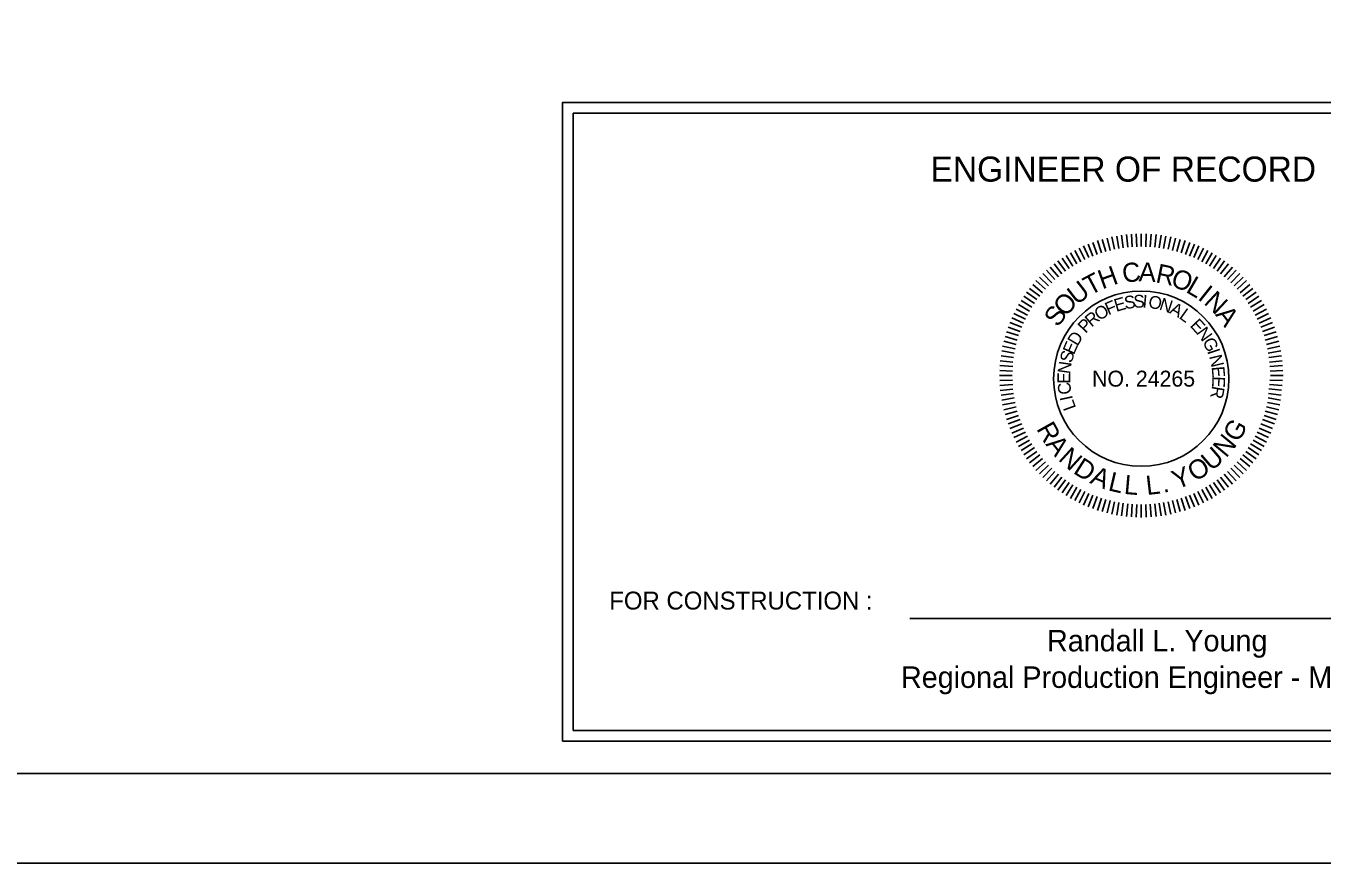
# Model space of a CAD drawing. Extents: x -796 to 2793, y -4650 to 4425.
# Drawn here: x 2234 to 2596, y 1000 to 1233.8 of the extents above; entities that cross this region are included whole.
import ezdxf

# ---------------------------------------------------------------- set-up
doc = ezdxf.new("R2010")
doc.units = 0
for name, color, linetype in [('RD_HC_CL', 7, 'Continuous'), ('RD_HC_Data', 7, 'Continuous'), ('RD_HC_Data_Tic', 7, 'Continuous'), ('RD_SHT_Bndy', 7, 'Continuous'), ('RD_TX_PEShield', 7, 'Continuous')]:
    doc.layers.add(name, color=color, linetype=linetype)

msp = doc.modelspace()

# ---------------------------------------------------------------- linework, layer by layer
at = {"layer": 'RD_HC_CL'}
msp.add_lwpolyline([(984.13, 2100), (2780.13, 2100), (2780.13, 1000), (984.13, 1000)], close=True, dxfattribs=at)
at = {"layer": 'RD_HC_Data'}
for p, q in [((2480.88, 1068.27), (2619.52, 1068.27)), ((2760, 1000), (1000, 1000)), ((1000, 1000), (2759.98, 1000))]:
    msp.add_line(p, q, dxfattribs=at)
for points in [[(1079.63, 2075.05), (2755.13, 2075.05), (2755.13, 1025), (1079.63, 1025)], [(2383.87, 1034.06), (2702.13, 1034.06), (2702.13, 1212.42), (2383.87, 1212.42)], [(2386.87, 1037.06), (2699.13, 1037.06), (2699.13, 1209.42), (2386.87, 1209.42)]]:
    msp.add_lwpolyline(points, close=True, dxfattribs=at)
at = {"layer": 'RD_TX_PEShield'}
for p, q in [((2531.98, 1169.54), (2530.65, 1172.84)), ((2531.98, 1169.54), (2530.65, 1172.84)), ((2533.16, 1169.99), (2531.94, 1173.33)), ((2533.16, 1169.99), (2531.94, 1173.33)), ((2534.33, 1170.44), (2533.23, 1173.83)), ((2534.33, 1170.44), (2533.23, 1173.83)), ((2535.55, 1170.77), (2534.57, 1174.18)), ((2535.55, 1170.77), (2534.57, 1174.18)), ((2536.76, 1171.09), (2535.9, 1174.54)), ((2536.76, 1171.09), (2535.9, 1174.54)), ((2537.98, 1171.42), (2537.24, 1174.9)), ((2537.98, 1171.42), (2537.24, 1174.9)), ((2539.22, 1171.61), (2538.6, 1175.12)), ((2539.22, 1171.61), (2538.6, 1175.12)), ((2540.46, 1171.81), (2539.97, 1175.33)), ((2540.46, 1171.81), (2539.97, 1175.33)), ((2541.7, 1172.01), (2541.33, 1175.55)), ((2541.7, 1172.01), (2541.33, 1175.55)), ((2542.96, 1172.07), (2542.71, 1175.62)), ((2542.96, 1172.07), (2542.71, 1175.62)), ((2544.21, 1172.14), (2544.09, 1175.69)), ((2544.21, 1172.14), (2544.09, 1175.69)), ((2545.47, 1172.2), (2545.47, 1175.76)), ((2545.47, 1172.2), (2545.47, 1175.76)), ((2546.73, 1172.14), (2546.85, 1175.69)), ((2546.73, 1172.14), (2546.85, 1175.69)), ((2547.98, 1172.07), (2548.23, 1175.62)), ((2547.98, 1172.07), (2548.23, 1175.62)), ((2549.24, 1172.01), (2549.61, 1175.55)), ((2549.24, 1172.01), (2549.61, 1175.55)), ((2550.48, 1171.81), (2550.98, 1175.33)), ((2550.48, 1171.81), (2550.98, 1175.33)), ((2551.72, 1171.61), (2552.34, 1175.12)), ((2551.72, 1171.61), (2552.34, 1175.12)), ((2552.96, 1171.42), (2553.71, 1174.9)), ((2552.96, 1171.42), (2553.71, 1174.9)), ((2552.96, 1171.42), (2553.71, 1174.9)), ((2554.18, 1171.09), (2555.04, 1174.54)), ((2554.18, 1171.09), (2555.04, 1174.54)), ((2554.18, 1171.09), (2555.04, 1174.54)), ((2555.39, 1170.77), (2556.37, 1174.18)), ((2555.39, 1170.77), (2556.37, 1174.18)), ((2555.39, 1170.77), (2556.37, 1174.18)), ((2556.61, 1170.44), (2557.71, 1173.83)), ((2556.61, 1170.44), (2557.71, 1173.83)), ((2556.61, 1170.44), (2557.71, 1173.83)), ((2557.78, 1169.99), (2559, 1173.33)), ((2557.78, 1169.99), (2559, 1173.33)), ((2557.78, 1169.99), (2559, 1173.33)), ((2558.96, 1169.54), (2560.29, 1172.84)), ((2558.96, 1169.54), (2560.29, 1172.84)), ((2558.96, 1169.54), (2560.29, 1172.84)), ((2526.39, 1166.69), (2524.51, 1169.71)), ((2526.39, 1166.69), (2524.51, 1169.71)), ((2527.45, 1167.38), (2525.67, 1170.46)), ((2527.45, 1167.38), (2525.67, 1170.46)), ((2528.57, 1167.95), (2526.9, 1171.09)), ((2528.57, 1167.95), (2526.9, 1171.09)), ((2529.69, 1168.52), (2528.13, 1171.71)), ((2529.69, 1168.52), (2528.13, 1171.71)), ((2530.81, 1169.09), (2529.36, 1172.34)), ((2530.81, 1169.09), (2529.36, 1172.34)), ((2560.13, 1169.09), (2561.58, 1172.34)), ((2560.13, 1169.09), (2561.58, 1172.34)), ((2560.13, 1169.09), (2561.58, 1172.34)), ((2561.25, 1168.52), (2562.81, 1171.71)), ((2561.25, 1168.52), (2562.81, 1171.71)), ((2561.25, 1168.52), (2562.81, 1171.71)), ((2562.37, 1167.95), (2564.04, 1171.09)), ((2562.37, 1167.95), (2564.04, 1171.09)), ((2562.37, 1167.95), (2564.04, 1171.09)), ((2563.49, 1167.38), (2565.27, 1170.46)), ((2563.49, 1167.38), (2565.27, 1170.46)), ((2563.49, 1167.38), (2565.27, 1170.46)), ((2564.55, 1166.69), (2566.43, 1169.71)), ((2564.55, 1166.69), (2566.43, 1169.71)), ((2564.55, 1166.69), (2566.43, 1169.71)), ((2521.35, 1162.95), (2518.97, 1165.59)), ((2521.35, 1162.95), (2518.97, 1165.59)), ((2522.33, 1163.74), (2520.04, 1166.46)), ((2522.33, 1163.74), (2520.04, 1166.46)), ((2523.31, 1164.53), (2521.12, 1167.33)), ((2523.31, 1164.53), (2521.12, 1167.33)), ((2524.28, 1165.32), (2522.19, 1168.2)), ((2524.28, 1165.32), (2522.19, 1168.2)), ((2525.34, 1166.01), (2523.35, 1168.95)), ((2525.34, 1166.01), (2523.35, 1168.95)), ((2565.6, 1166.01), (2567.59, 1168.95)), ((2565.6, 1166.01), (2567.59, 1168.95)), ((2565.6, 1166.01), (2567.59, 1168.95)), ((2566.66, 1165.32), (2568.75, 1168.2)), ((2566.66, 1165.32), (2568.75, 1168.2)), ((2566.66, 1165.32), (2568.75, 1168.2)), ((2567.64, 1164.53), (2569.82, 1167.33)), ((2567.64, 1164.53), (2569.82, 1167.33)), ((2567.64, 1164.53), (2569.82, 1167.33)), ((2568.61, 1163.74), (2570.9, 1166.46)), ((2568.61, 1163.74), (2570.9, 1166.46)), ((2568.61, 1163.74), (2570.9, 1166.46)), ((2569.59, 1162.95), (2571.97, 1165.59)), ((2569.59, 1162.95), (2571.97, 1165.59)), ((2569.59, 1162.95), (2571.97, 1165.59)), ((2518.68, 1160.28), (2516.04, 1162.66)), ((2518.68, 1160.28), (2516.04, 1162.66)), ((2519.57, 1161.17), (2517.02, 1163.64)), ((2519.57, 1161.17), (2517.02, 1163.64)), ((2520.46, 1162.06), (2517.99, 1164.61)), ((2520.46, 1162.06), (2517.99, 1164.61)), ((2570.48, 1162.06), (2572.95, 1164.61)), ((2570.48, 1162.06), (2572.95, 1164.61)), ((2570.48, 1162.06), (2572.95, 1164.61)), ((2571.37, 1161.17), (2573.93, 1163.64)), ((2571.37, 1161.17), (2573.93, 1163.64)), ((2571.37, 1161.17), (2573.93, 1163.64)), ((2572.26, 1160.28), (2574.9, 1162.66)), ((2572.26, 1160.28), (2574.9, 1162.66)), ((2572.26, 1160.28), (2574.9, 1162.66)), ((2515.62, 1156.29), (2512.68, 1158.28)), ((2515.62, 1156.29), (2512.68, 1158.28)), ((2516.31, 1157.35), (2513.43, 1159.44)), ((2516.31, 1157.35), (2513.43, 1159.44)), ((2517.1, 1158.32), (2514.3, 1160.51)), ((2517.1, 1158.32), (2514.3, 1160.51)), ((2517.89, 1159.3), (2515.17, 1161.59)), ((2517.89, 1159.3), (2515.17, 1161.59)), ((2573.05, 1159.3), (2575.77, 1161.59)), ((2573.05, 1159.3), (2575.77, 1161.59)), ((2573.05, 1159.3), (2575.77, 1161.59)), ((2573.84, 1158.32), (2576.64, 1160.51)), ((2573.84, 1158.32), (2576.64, 1160.51)), ((2573.84, 1158.32), (2576.64, 1160.51)), ((2574.63, 1157.35), (2577.51, 1159.44)), ((2574.63, 1157.35), (2577.51, 1159.44)), ((2574.63, 1157.35), (2577.51, 1159.44)), ((2575.32, 1156.29), (2578.26, 1158.28)), ((2575.32, 1156.29), (2578.26, 1158.28)), ((2575.32, 1156.29), (2578.26, 1158.28)), ((2513.68, 1153.06), (2510.54, 1154.73)), ((2513.68, 1153.06), (2510.54, 1154.73)), ((2514.25, 1154.18), (2511.17, 1155.96)), ((2514.25, 1154.18), (2511.17, 1155.96)), ((2514.94, 1155.24), (2511.92, 1157.12)), ((2514.94, 1155.24), (2511.92, 1157.12)), ((2576, 1155.24), (2579.02, 1157.12)), ((2576, 1155.24), (2579.02, 1157.12)), ((2576, 1155.24), (2579.02, 1157.12)), ((2576.69, 1154.18), (2579.77, 1155.96)), ((2576.69, 1154.18), (2579.77, 1155.96)), ((2576.69, 1154.18), (2579.77, 1155.96)), ((2577.26, 1153.06), (2580.4, 1154.73)), ((2577.26, 1153.06), (2580.4, 1154.73)), ((2577.26, 1153.06), (2580.4, 1154.73)), ((2512.54, 1150.82), (2509.29, 1152.27)), ((2512.54, 1150.82), (2509.29, 1152.27)), ((2513.11, 1151.94), (2509.92, 1153.5)), ((2513.11, 1151.94), (2509.92, 1153.5)), ((2577.83, 1151.94), (2581.02, 1153.5)), ((2577.83, 1151.94), (2581.02, 1153.5)), ((2577.83, 1151.94), (2581.02, 1153.5)), ((2578.4, 1150.82), (2581.65, 1152.27)), ((2578.4, 1150.82), (2581.65, 1152.27)), ((2578.4, 1150.82), (2581.65, 1152.27)), ((2511.19, 1147.3), (2507.8, 1148.4)), ((2511.19, 1147.3), (2507.8, 1148.4)), ((2511.64, 1148.47), (2508.3, 1149.69)), ((2511.64, 1148.47), (2508.3, 1149.69)), ((2512.09, 1149.65), (2508.79, 1150.98)), ((2512.09, 1149.65), (2508.79, 1150.98)), ((2578.85, 1149.65), (2582.15, 1150.98)), ((2578.85, 1149.65), (2582.15, 1150.98)), ((2578.85, 1149.65), (2582.15, 1150.98)), ((2579.3, 1148.47), (2582.64, 1149.69)), ((2579.3, 1148.47), (2582.64, 1149.69)), ((2579.3, 1148.47), (2582.64, 1149.69)), ((2579.75, 1147.3), (2583.14, 1148.4)), ((2579.75, 1147.3), (2583.14, 1148.4)), ((2579.75, 1147.3), (2583.14, 1148.4)), ((2510.21, 1143.65), (2506.73, 1144.39)), ((2510.21, 1143.65), (2506.73, 1144.39)), ((2510.54, 1144.87), (2507.09, 1145.73)), ((2510.54, 1144.87), (2507.09, 1145.73)), ((2510.86, 1146.08), (2507.45, 1147.06)), ((2510.86, 1146.08), (2507.45, 1147.06)), ((2580.08, 1146.08), (2583.5, 1147.06)), ((2580.08, 1146.08), (2583.5, 1147.06)), ((2580.08, 1146.08), (2583.5, 1147.06)), ((2580.4, 1144.87), (2583.85, 1145.73)), ((2580.4, 1144.87), (2583.85, 1145.73)), ((2580.4, 1144.87), (2583.85, 1145.73)), ((2580.73, 1143.65), (2584.21, 1144.39)), ((2580.73, 1143.65), (2584.21, 1144.39)), ((2580.73, 1143.65), (2584.21, 1144.39)), ((2509.62, 1139.93), (2506.08, 1140.3)), ((2509.62, 1139.93), (2506.08, 1140.3)), ((2509.82, 1141.17), (2506.3, 1141.67)), ((2509.82, 1141.17), (2506.3, 1141.67)), ((2510.02, 1142.41), (2506.52, 1143.03)), ((2510.02, 1142.41), (2506.52, 1143.03)), ((2580.92, 1142.41), (2584.43, 1143.03)), ((2580.92, 1142.41), (2584.43, 1143.03)), ((2580.92, 1142.41), (2584.43, 1143.03)), ((2581.12, 1141.17), (2584.64, 1141.67)), ((2581.12, 1141.17), (2584.64, 1141.67)), ((2581.12, 1141.17), (2584.64, 1141.67)), ((2581.32, 1139.93), (2584.86, 1140.3)), ((2581.32, 1139.93), (2584.86, 1140.3)), ((2581.32, 1139.93), (2584.86, 1140.3)), ((2509.49, 1137.42), (2505.94, 1137.54)), ((2509.49, 1137.42), (2505.94, 1137.54)), ((2509.56, 1138.67), (2506.01, 1138.92)), ((2509.56, 1138.67), (2506.01, 1138.92)), ((2581.38, 1138.67), (2584.93, 1138.92)), ((2581.38, 1138.67), (2584.93, 1138.92)), ((2581.38, 1138.67), (2584.93, 1138.92)), ((2581.45, 1137.42), (2585, 1137.54)), ((2581.45, 1137.42), (2585, 1137.54)), ((2581.45, 1137.42), (2585, 1137.54)), ((2509.43, 1136.16), (2505.87, 1136.16)), ((2509.43, 1136.16), (2505.87, 1136.16)), ((2509.49, 1134.9), (2505.94, 1134.78)), ((2509.49, 1134.9), (2505.94, 1134.78)), ((2509.56, 1133.65), (2506.01, 1133.4)), ((2509.56, 1133.65), (2506.01, 1133.4)), ((2581.25, 1133.66), (2584.79, 1133.41)), ((2581.25, 1133.66), (2584.79, 1133.41)), ((2581.38, 1134.91), (2584.93, 1134.78)), ((2581.38, 1134.91), (2584.93, 1134.78)), ((2581.52, 1136.16), (2585.08, 1136.16)), ((2581.52, 1136.16), (2585.08, 1136.16)), ((2581.52, 1136.16), (2585.08, 1136.16)), ((2509.62, 1132.39), (2506.08, 1132.02)), ((2509.62, 1132.39), (2506.08, 1132.02)), ((2509.82, 1131.15), (2506.3, 1130.65)), ((2509.82, 1131.15), (2506.3, 1130.65)), ((2510.02, 1129.91), (2506.52, 1129.29)), ((2510.02, 1129.91), (2506.52, 1129.29)), ((2580.86, 1129.92), (2584.36, 1129.3)), ((2580.86, 1129.92), (2584.36, 1129.3)), ((2580.99, 1131.17), (2584.5, 1130.67)), ((2580.99, 1131.17), (2584.5, 1130.67)), ((2581.12, 1132.41), (2584.64, 1132.04)), ((2581.12, 1132.41), (2584.64, 1132.04)), ((2510.21, 1128.67), (2506.73, 1127.93)), ((2510.21, 1128.67), (2506.73, 1127.93)), ((2510.54, 1127.45), (2507.09, 1126.59)), ((2510.54, 1127.45), (2507.09, 1126.59)), ((2510.86, 1126.24), (2507.45, 1125.26)), ((2510.86, 1126.24), (2507.45, 1125.26)), ((2580.08, 1126.24), (2583.5, 1125.26)), ((2580.08, 1126.24), (2583.5, 1125.26)), ((2580.4, 1127.45), (2583.85, 1126.59)), ((2580.4, 1127.45), (2583.85, 1126.59)), ((2580.73, 1128.67), (2584.21, 1127.93)), ((2580.73, 1128.67), (2584.21, 1127.93)), ((2511.19, 1125.02), (2507.8, 1123.92)), ((2511.64, 1123.85), (2508.3, 1122.63)), ((2511.64, 1123.85), (2508.3, 1122.63)), ((2512.09, 1122.67), (2508.79, 1121.34)), ((2512.09, 1122.67), (2508.79, 1121.34)), ((2578.85, 1122.67), (2582.15, 1121.34)), ((2578.85, 1122.67), (2582.15, 1121.34)), ((2579.3, 1123.85), (2582.64, 1122.63)), ((2579.3, 1123.85), (2582.64, 1122.63)), ((2579.75, 1125.02), (2583.14, 1123.92)), ((2579.75, 1125.02), (2583.14, 1123.92)), ((2512.54, 1121.5), (2509.29, 1120.05)), ((2512.54, 1121.5), (2509.29, 1120.05)), ((2513.11, 1120.38), (2509.92, 1118.82)), ((2513.11, 1120.38), (2509.92, 1118.82)), ((2513.68, 1119.26), (2510.54, 1117.59)), ((2513.68, 1119.26), (2510.54, 1117.59)), ((2577.26, 1119.26), (2580.4, 1117.59)), ((2577.26, 1119.26), (2580.4, 1117.59)), ((2577.83, 1120.38), (2581.02, 1118.82)), ((2577.83, 1120.38), (2581.02, 1118.82)), ((2578.4, 1121.5), (2581.65, 1120.05)), ((2578.4, 1121.5), (2581.65, 1120.05)), ((2514.25, 1118.14), (2511.17, 1116.36)), ((2514.25, 1118.14), (2511.17, 1116.36)), ((2514.94, 1117.08), (2511.92, 1115.2)), ((2514.94, 1117.08), (2511.92, 1115.2)), ((2515.62, 1116.03), (2512.68, 1114.04)), ((2515.62, 1116.03), (2512.68, 1114.04)), ((2516.31, 1114.97), (2513.43, 1112.88)), ((2516.31, 1114.97), (2513.43, 1112.88)), ((2574.63, 1114.97), (2577.51, 1112.88)), ((2574.63, 1114.97), (2577.51, 1112.88)), ((2575.32, 1116.03), (2578.26, 1114.04)), ((2575.32, 1116.03), (2578.26, 1114.04)), ((2576, 1117.08), (2579.02, 1115.2)), ((2576, 1117.08), (2579.02, 1115.2)), ((2576.69, 1118.14), (2579.77, 1116.36)), ((2576.69, 1118.14), (2579.77, 1116.36)), ((2517.1, 1114), (2514.3, 1111.81)), ((2517.1, 1114), (2514.3, 1111.81)), ((2517.89, 1113.02), (2515.17, 1110.73)), ((2517.89, 1113.02), (2515.17, 1110.73)), ((2518.68, 1112.04), (2516.04, 1109.66)), ((2518.68, 1112.04), (2516.04, 1109.66)), ((2572.26, 1112.04), (2574.9, 1109.66)), ((2572.26, 1112.04), (2574.9, 1109.66)), ((2573.05, 1113.02), (2575.77, 1110.73)), ((2573.05, 1113.02), (2575.77, 1110.73)), ((2573.84, 1114), (2576.64, 1111.81)), ((2573.84, 1114), (2576.64, 1111.81)), ((2519.57, 1111.15), (2517.02, 1108.68)), ((2519.57, 1111.15), (2517.02, 1108.68)), ((2520.46, 1110.26), (2517.99, 1107.71)), ((2520.46, 1110.26), (2517.99, 1107.71)), ((2521.35, 1109.37), (2518.97, 1106.73)), ((2521.35, 1109.37), (2518.97, 1106.73)), ((2522.33, 1108.58), (2520.04, 1105.86)), ((2522.33, 1108.58), (2520.04, 1105.86)), ((2523.31, 1107.79), (2521.12, 1104.99)), ((2523.31, 1107.79), (2521.12, 1104.99)), ((2567.64, 1107.79), (2569.82, 1104.99)), ((2567.64, 1107.79), (2569.82, 1104.99)), ((2568.61, 1108.58), (2570.9, 1105.86)), ((2568.61, 1108.58), (2570.9, 1105.86)), ((2569.59, 1109.37), (2571.97, 1106.73)), ((2570.48, 1110.26), (2572.95, 1107.71)), ((2570.48, 1110.26), (2572.95, 1107.71)), ((2571.37, 1111.15), (2573.93, 1108.68)), ((2571.37, 1111.15), (2573.93, 1108.68)), ((2524.28, 1107), (2522.19, 1104.12)), ((2524.28, 1107), (2522.19, 1104.12)), ((2525.34, 1106.31), (2523.35, 1103.37)), ((2525.34, 1106.31), (2523.35, 1103.37)), ((2526.39, 1105.63), (2524.51, 1102.61)), ((2526.39, 1105.63), (2524.51, 1102.61)), ((2527.45, 1104.94), (2525.67, 1101.86)), ((2527.45, 1104.94), (2525.67, 1101.86)), ((2528.57, 1104.37), (2526.9, 1101.23)), ((2528.57, 1104.37), (2526.9, 1101.23)), ((2562.37, 1104.37), (2564.04, 1101.23)), ((2562.37, 1104.37), (2564.04, 1101.23)), ((2563.49, 1104.94), (2565.27, 1101.86)), ((2563.49, 1104.94), (2565.27, 1101.86)), ((2564.55, 1105.63), (2566.43, 1102.61)), ((2564.55, 1105.63), (2566.43, 1102.61)), ((2565.6, 1106.31), (2567.59, 1103.37)), ((2565.6, 1106.31), (2567.59, 1103.37)), ((2566.66, 1107), (2568.75, 1104.12)), ((2566.66, 1107), (2568.75, 1104.12)), ((2529.69, 1103.8), (2528.13, 1100.61)), ((2529.69, 1103.8), (2528.13, 1100.61)), ((2530.81, 1103.23), (2529.36, 1099.98)), ((2530.81, 1103.23), (2529.36, 1099.98)), ((2531.98, 1102.78), (2530.65, 1099.48)), ((2531.98, 1102.78), (2530.65, 1099.48)), ((2533.16, 1102.33), (2531.94, 1098.99)), ((2533.16, 1102.33), (2531.94, 1098.99)), ((2534.33, 1101.88), (2533.23, 1098.49)), ((2534.33, 1101.88), (2533.23, 1098.49)), ((2535.55, 1101.55), (2534.57, 1098.14)), ((2535.55, 1101.55), (2534.57, 1098.14)), ((2536.76, 1101.23), (2535.9, 1097.78)), ((2536.76, 1101.23), (2535.9, 1097.78)), ((2537.98, 1100.9), (2537.24, 1097.42)), ((2537.98, 1100.9), (2537.24, 1097.42)), ((2539.22, 1100.71), (2538.6, 1097.2)), ((2539.22, 1100.71), (2538.6, 1097.2)), ((2540.46, 1100.51), (2539.97, 1096.99)), ((2540.46, 1100.51), (2539.97, 1096.99)), ((2550.48, 1100.51), (2550.98, 1096.99)), ((2550.48, 1100.51), (2550.98, 1096.99)), ((2551.72, 1100.71), (2552.34, 1097.2)), ((2551.72, 1100.71), (2552.34, 1097.2)), ((2552.96, 1100.9), (2553.71, 1097.42)), ((2552.96, 1100.9), (2553.71, 1097.42)), ((2554.18, 1101.23), (2555.04, 1097.78)), ((2554.18, 1101.23), (2555.04, 1097.78)), ((2555.39, 1101.55), (2556.37, 1098.14)), ((2555.39, 1101.55), (2556.37, 1098.14)), ((2556.61, 1101.88), (2557.71, 1098.49)), ((2556.61, 1101.88), (2557.71, 1098.49)), ((2557.78, 1102.33), (2559, 1098.99)), ((2557.78, 1102.33), (2559, 1098.99)), ((2558.96, 1102.78), (2560.29, 1099.48)), ((2558.96, 1102.78), (2560.29, 1099.48)), ((2560.13, 1103.23), (2561.58, 1099.98)), ((2560.13, 1103.23), (2561.58, 1099.98)), ((2561.25, 1103.8), (2562.81, 1100.61)), ((2561.25, 1103.8), (2562.81, 1100.61)), ((2541.7, 1100.31), (2541.33, 1096.77)), ((2541.7, 1100.31), (2541.33, 1096.77)), ((2542.96, 1100.25), (2542.71, 1096.7)), ((2542.96, 1100.25), (2542.71, 1096.7)), ((2544.21, 1100.18), (2544.09, 1096.63)), ((2544.21, 1100.18), (2544.09, 1096.63)), ((2545.47, 1100.11), (2545.47, 1096.55)), ((2545.47, 1100.11), (2545.47, 1096.55)), ((2546.73, 1100.18), (2546.85, 1096.63)), ((2546.73, 1100.18), (2546.85, 1096.63)), ((2547.98, 1100.25), (2548.23, 1096.7)), ((2547.98, 1100.25), (2548.23, 1096.7)), ((2549.24, 1100.31), (2549.61, 1096.77)), ((2549.24, 1100.31), (2549.61, 1096.77))]:
    msp.add_line(p, q, dxfattribs=at)
msp.add_circle((2545.47, 1135.28), 24.48, dxfattribs=at)

# ---------------------------------------------------------------- texts
at = {"layer": 'RD_HC_Data_Tic'}
for s, height, p in [('ENGINEER OF RECORD', 7, (2486.62, 1190.31)), ('FOR CONSTRUCTION :', 5.0001, (2396.9, 1070.81))]:
    msp.add_text(s, height=height, dxfattribs=at).set_placement(p)
at = {"layer": 'RD_SHT_Bndy'}
for s, p in [('Randall L. Young', (2519.15, 1059.12)), ('Regional Production Engineer - Midlands', (2478.37, 1048.92))]:
    msp.add_text(s, height=6, dxfattribs=at).set_placement(p)
at = {"layer": 'RD_TX_PEShield'}
for s, height, rotation, p in [('H', 5.34, 19.9102, (2534.57, 1160.2)), ('C', 5.34, 6.8832, (2540.46, 1162.02)), ('A', 5.34, 357.9448, (2544.68, 1162.47)), ('R', 5.34, 348.267, (2549.26, 1162.22)), ('O', 5.34, 339.3286, (2553.4, 1161.3)), ('U', 5.34, 37.7726, (2527.45, 1155.66)), ('T', 5.34, 28.0947, (2531.13, 1158.4)), ('L', 5.34, 329.6507, (2557.66, 1159.6)), ('O', 5.34, 47.4504, (2524.28, 1152.34)), ('S', 3.56, 8.6909, (2540.96, 1154.67)), ('S', 3.56, 1.79, (2543.32, 1155.07)), ('I', 3.56, 354.889, (2545.71, 1155.19)), ('O', 3.56, 350.4045, (2547.27, 1155.11)), ('I', 5.34, 321.4663, (2561, 1157.62)), ('N', 5.34, 317.0007, (2562.69, 1156.34)), ('S', 5.34, 54.9027, (2522.25, 1149.44)), ('O', 3.56, 31.7869, (2533.72, 1151.35)), ('F', 3.56, 23.0853, (2536.28, 1152.94)), ('E', 3.56, 16.1843, (2538.47, 1153.92)), ('N', 3.56, 341.7029, (2550.25, 1154.61)), ('A', 3.56, 333.0013, (2553.12, 1153.66)), ('L', 3.56, 324.2997, (2555.81, 1152.29)), ('A', 5.34, 307.3229, (2565.99, 1153.14)), ('P', 3.56, 46.7912, (2529.96, 1147.75)), ('R', 3.56, 39.8902, (2531.57, 1149.53)), ('E', 3.56, 313.2251, (2558.88, 1149.99)), ('D', 3.56, 59.074, (2527.66, 1144.17)), ('N', 3.56, 305.7317, (2560.69, 1148.11)), ('E', 3.56, 66.5674, (2526.65, 1141.77)), ('G', 3.56, 297.0301, (2562.45, 1145.66)), ('S', 3.56, 73.4683, (2526.01, 1139.46)), ('I', 3.56, 288.3285, (2563.83, 1142.98)), ('N', 3.56, 283.8441, (2564.38, 1141.52)), ('E', 3.56, 89.6633, (2525.62, 1133.87)), ('N', 3.56, 82.17, (2525.6, 1136.47)), ('E', 3.56, 275.1424, (2565.1, 1138.59)), ('C', 3.56, 97.7667, (2526.01, 1131.08)), ('R', 3.56, 260.1557, (2565.29, 1133.4)), ('E', 3.56, 267.6491, (2565.36, 1136)), ('I', 3.56, 102.2511, (2526.4, 1129.57)), ('L', 3.56, 109.7445, (2527.31, 1127.14)), ('R', 5.34, 299.1493, (2516.07, 1121.31)), ('G', 5.34, 60.1113, (2572.58, 1117.26)), ('A', 5.34, 308.0877, (2518.6, 1116.91)), ('N', 5.34, 50.4335, (2569.16, 1112.96)), ('N', 5.34, 317.7655, (2522.07, 1112.65)), ('U', 5.34, 40.7556, (2565.07, 1109.29)), ('D', 5.34, 327.4433, (2526.2, 1109.04)), ('O', 5.34, 31.0778, (2560.43, 1106.37)), ('A', 5.34, 337.1212, (2530.89, 1106.18)), ('L', 5.34, 346.799, (2535.99, 1104.14)), ('L', 5.34, 354.9835, (2540.52, 1103.11)), ('L', 5.34, 6.5171, (2547.05, 1102.77)), ('Y', 5.34, 21.4, (2555.35, 1104.26)), ('.', 5.34, 14.7016, (2551.67, 1103.32))]:
    msp.add_text(s, height=height, rotation=rotation, dxfattribs=at).set_placement(p)
msp.add_text('NO. 24265', height=4.45, dxfattribs=at).set_placement((2531.72, 1133.06))

doc.saveas('drawing.dxf')
